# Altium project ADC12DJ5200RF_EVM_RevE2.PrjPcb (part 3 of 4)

## Sheet GPIO2_RevE2.SchDoc: EVM I2C/SPI
size 431 x 279 mm; Date: Not shown in title block; ApprovedBy: Not shown in title block; CheckedBy: Not shown in title block; Author: Not shown in title block; CompanyName: Not shown in title block; DrawnBy: DWG; Engineer: DWG; Organization: Not shown in title block; Address1: Not shown in title block; Address2: Not shown in title block; Address3: Not shown in title block; Address4: Not shown in title block; DocumentNumber: 10; Revision: Use project parameter SCH_Rev; SheetNumber: 10; SheetTotal: 15; PageSetup: Record=PageOptions¦CenterHorizontal=True¦CenterVertical=True¦PrintScale=1.00¦XCorrection=1.00¦YCorrection=1.00¦PrintKind=0¦BorderSize=5000000¦LeftOffset=0¦BottomOffset=0¦Orientation=2¦PaperLength=1000¦PaperWidth=1000¦Scale=100¦PaperSource=15¦PrintQuality=600¦MediaType=1¦DitherType=10¦PaperKind=Letter¦PrintScaleMode=1
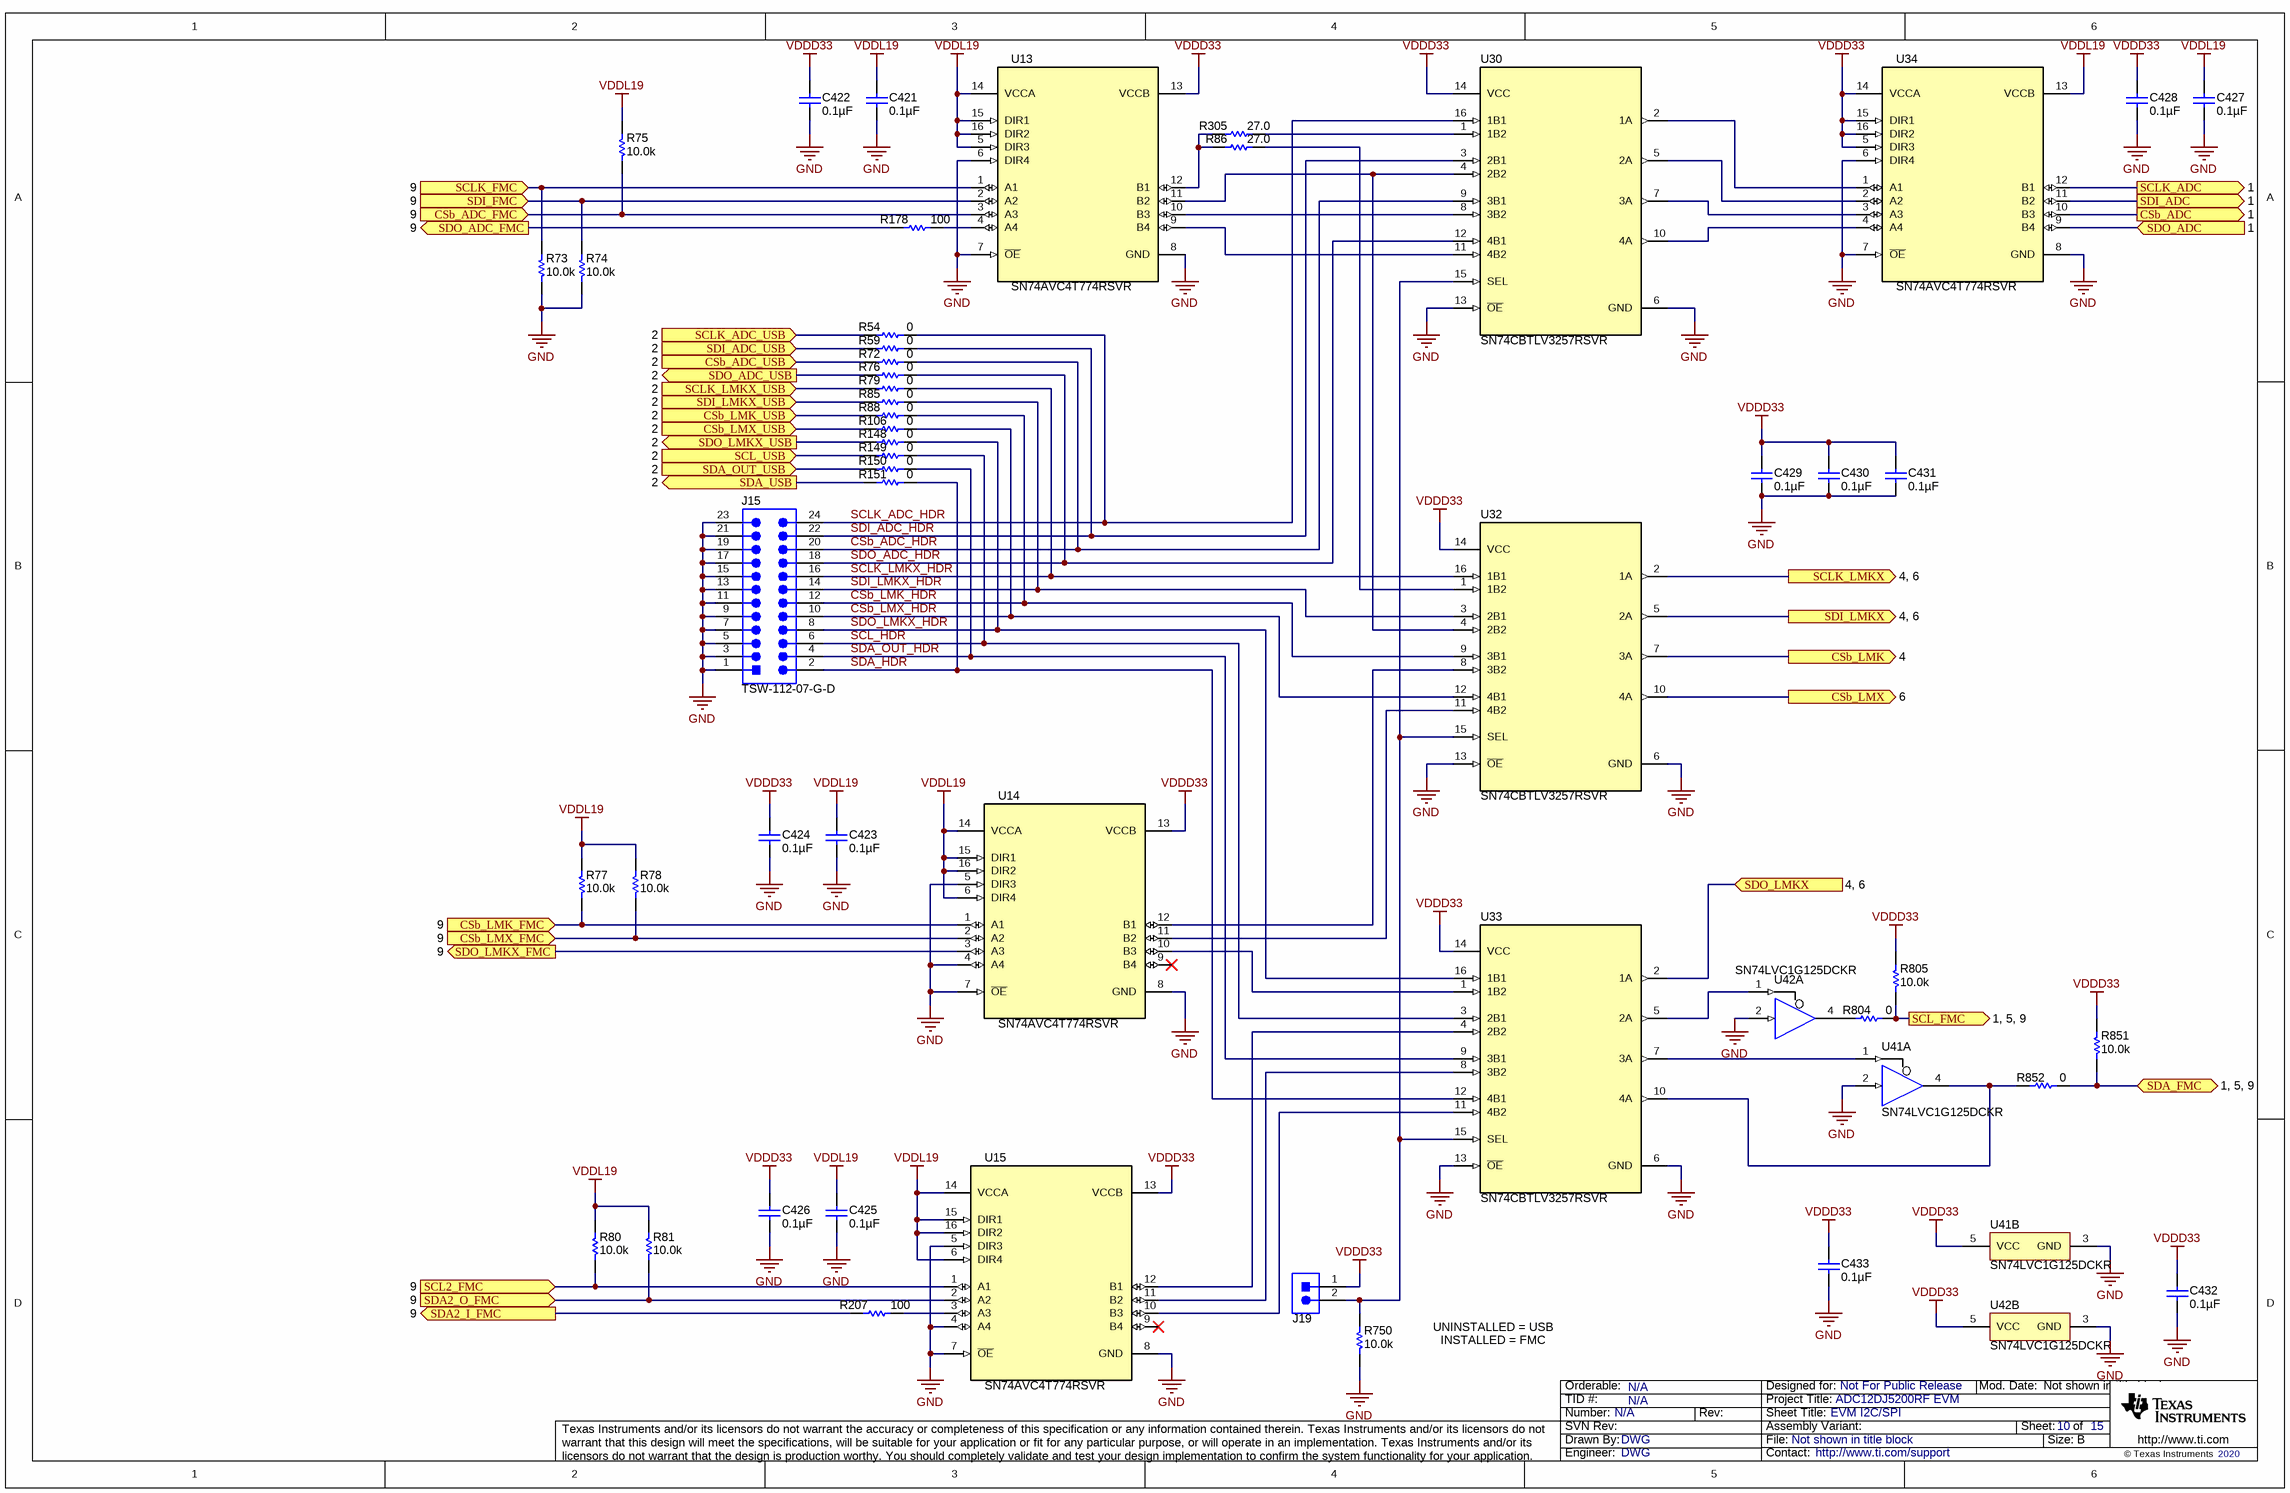
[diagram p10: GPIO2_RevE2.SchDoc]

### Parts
C421  ValueDisplayed: 0.1µF  [0201_033L]  (hidden comment: 0201BB104KW160)
C422  ValueDisplayed: 0.1µF  [0201_033L]  (hidden comment: 0201BB104KW160)
C423  ValueDisplayed: 0.1µF  [0201_033L]  (hidden comment: 0201BB104KW160)
C424  ValueDisplayed: 0.1µF  [0201_033L]  (hidden comment: 0201BB104KW160)
C425  ValueDisplayed: 0.1µF  [0201_033L]  (hidden comment: 0201BB104KW160)
C426  ValueDisplayed: 0.1µF  [0201_033L]  (hidden comment: 0201BB104KW160)
C427  ValueDisplayed: 0.1µF  [0201_033L]  (hidden comment: 0201BB104KW160)
C428  ValueDisplayed: 0.1µF  [0201_033L]  (hidden comment: 0201BB104KW160)
C429  ValueDisplayed: 0.1µF  [0201_033L]  (hidden comment: 0201BB104KW160)
C430  ValueDisplayed: 0.1µF  [0201_033L]  (hidden comment: 0201BB104KW160)
C431  ValueDisplayed: 0.1µF  [0201_033L]  (hidden comment: 0201BB104KW160)
C432  ValueDisplayed: 0.1µF  [0201_033L]  (hidden comment: 0201BB104KW160)
C433  ValueDisplayed: 0.1µF  [0201_033L]  (hidden comment: 0201BB104KW160)
J15  TSW-112-07-G-D  [TSW-112-07-G-D]
J19  5-146261-1  [CONN_5-146261-1]  (value not drawn)
R54  ValueDisplayed: 0  [0201L]  (hidden comment: CRCW02010000Z0ED)
R59  ValueDisplayed: 0  [0201L]  (hidden comment: CRCW02010000Z0ED)
R72  ValueDisplayed: 0  [0201L]  (hidden comment: CRCW02010000Z0ED)
R73  ValueDisplayed: 10.0k  [0201]  (hidden comment: CRCW02010000Z0ED)
R74  ValueDisplayed: 10.0k  [0201]  (hidden comment: CRCW02010000Z0ED)
R75  ValueDisplayed: 10.0k  [0201L]  (hidden comment: RC0201FR-7D10KL)
R76  ValueDisplayed: 0  [0201L]  (hidden comment: CRCW02010000Z0ED)
R77  ValueDisplayed: 10.0k  [0201L]  (hidden comment: RC0201FR-7D10KL)
R78  ValueDisplayed: 10.0k  [0201]  (hidden comment: CRCW02010000Z0ED)
R79  ValueDisplayed: 0  [0201L]  (hidden comment: CRCW02010000Z0ED)
R80  ValueDisplayed: 10.0k  [0201L]  (hidden comment: RC0201FR-7D10KL)
R81  ValueDisplayed: 10.0k  [0201L]  (hidden comment: RC0201FR-7D10KL)
R85  ValueDisplayed: 0  [0201L]  (hidden comment: CRCW02010000Z0ED)
R86  ValueDisplayed: 27.0  [0201L]  (hidden comment: RC0201FR-7D49R9L)
R88  ValueDisplayed: 0  [0201L]  (hidden comment: CRCW02010000Z0ED)
R106  ValueDisplayed: 0  [0201L]  (hidden comment: CRCW02010000Z0ED)
R148  ValueDisplayed: 0  [0201L]  (hidden comment: CRCW02010000Z0ED)
R149  ValueDisplayed: 0  [0201L]  (hidden comment: CRCW02010000Z0ED)
R150  ValueDisplayed: 0  [0201L]  (hidden comment: CRCW02010000Z0ED)
R151  ValueDisplayed: 0  [0201L]  (hidden comment: CRCW02010000Z0ED)
R178  ValueDisplayed: 100  [0201L]  (hidden comment: RC0201FS-7D100RL)
R207  ValueDisplayed: 100  [0201L]  (hidden comment: RC0201FS-7D100RL)
R305  ValueDisplayed: 27.0  [0201L]  (hidden comment: CRCW02010000Z0ED)
R750  ValueDisplayed: 10.0k  [0201L]  (hidden comment: RC0201FR-7D10KL)
R804  ValueDisplayed: 0  [0201L]  (hidden comment: CRCW02010000Z0ED)
R805  ValueDisplayed: 10.0k  [0201]  (hidden comment: RC0201FR-7D10KL)
R851  ValueDisplayed: 10.0k  [0201]  (hidden comment: RC0201FR-7D10KL)
R852  ValueDisplayed: 0  [0201L]  (hidden comment: CRCW02010000Z0ED)
U13  SN74AVC4T774RSVR  [RSV0016A]
U14  SN74AVC4T774RSVR  [RSV0016A]
U15  SN74AVC4T774RSVR  [RSV0016A]
U30  SN74CBTLV3257RSVR  [RSV0016A]
U32  SN74CBTLV3257RSVR  [RSV0016A]
U33  SN74CBTLV3257RSVR  [RSV0016A]
U34  SN74AVC4T774RSVR  [RSV0016A]
U41  SN74LVC1G125DCKR  [DCK0005A_N]  (parts A,B of 2)
U42  SN74LVC1G125DCKR  [DCK0005A_N]  (parts A,B of 2)

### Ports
CSb_ADC (out, see 1), CSb_ADC_FMC (in, see 9), CSb_ADC_USB (in, see 2), CSb_LMK (out, see 4), CSb_LMK_FMC (in, see 9), CSb_LMK_USB (in, see 2), CSb_LMX (out, see 6), CSb_LMX_FMC (in, see 9), CSb_LMX_USB (in, see 2), SCL2_FMC (in, see 9), SCL_FMC (out, see 1, 5, 9), SCL_USB (in, see 2), SCLK_ADC (out, see 1), SCLK_ADC_USB (in, see 2), SCLK_FMC (in, see 9), SCLK_LMKX (out, see 4, 6), SCLK_LMKX_USB (in, see 2), SDA2_I_FMC (out, see 9), SDA2_O_FMC (in, see 9), SDA_FMC (bidir, see 1, 5, 9), SDA_OUT_USB (in, see 2), SDA_USB (out, see 2), SDI_ADC (out, see 1), SDI_ADC_USB (in, see 2), SDI_FMC (in, see 9), SDI_LMKX (out, see 4, 6), SDI_LMKX_USB (in, see 2), SDO_ADC (in, see 1), SDO_ADC_FMC (out, see 9), SDO_ADC_USB (out, see 2), SDO_LMKX (in, see 4, 6), SDO_LMKX_FMC (out, see 9), SDO_LMKX_USB (out, see 2)

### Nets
GND: C421.2 C422.2 C423.2 C424.2 C425.2 C426.2 C427.2 C428.2 C429.2 C430.2 C431.2 C432.2 C433.2 J15.1 J15.3 J15.5 J15.7 J15.9 J15.11 J15.13 J15.15 J15.17 J15.19 J15.21 J15.23 R73.1 R74.1 R750.1 U13.6(DIR4) U13.7(~{OE}) U13.8(GND) U14.4(A4) U14.5(DIR3) U14.7(~{OE}) U14.8(GND) U15.4(A4) U15.5(DIR3) U15.7(~{OE}) U15.8(GND) U30.6(GND) U30.13(~{OE}) U32.6(GND) U32.13(~{OE}) U33.6(GND) U33.13(~{OE}) U34.6(DIR4) U34.7(~{OE}) U34.8(GND) U41.2(A) U41.3(GND) U42.2(A) U42.3(GND)
VDDD33: C422.1 C424.1 C426.1 C428.1 C429.1 C430.1 C431.1 C432.1 C433.1 J19.1 R805.2 R851.2 U13.13(VCCB) U14.13(VCCB) U15.13(VCCB) U30.14(VCC) U32.14(VCC) U33.14(VCC) U34.5(DIR3) U34.14(VCCA) U34.15(DIR1) U34.16(DIR2) U41.5(VCC) U42.5(VCC)
VDDL19: C421.1 C423.1 C425.1 C427.1 R75.1 R77.1 R78.1 R80.1 R81.1 U13.5(DIR3) U13.14(VCCA) U13.15(DIR1) U13.16(DIR2) U14.6(DIR4) U14.14(VCCA) U14.15(DIR1) U14.16(DIR2) U15.6(DIR4) U15.14(VCCA) U15.15(DIR1) U15.16(DIR2) U34.13(VCCB)
CSb_ADC: U34.10(B3) ; port CSb_ADC
CSb_ADC_FMC: R75.2 U13.3(A3) ; port CSb_ADC_FMC
CSb_ADC_HDR: J15.20 R72.2 U30.9(3B1)
CSb_ADC_USB: R72.1 ; port CSb_ADC_USB
CSb_LMK: U32.7(3A) ; port CSb_LMK
CSb_LMK_FMC: R77.2 U14.1(A1) ; port CSb_LMK_FMC
CSb_LMK_HDR: J15.12 R88.2 U32.9(3B1)
CSb_LMK_USB: R88.1 ; port CSb_LMK_USB
CSb_LMX: U32.10(4A) ; port CSb_LMX
CSb_LMX_FMC: R78.2 U14.2(A2) ; port CSb_LMX_FMC
CSb_LMX_HDR: J15.10 R106.2 U32.12(4B1)
CSb_LMX_USB: R106.1 ; port CSb_LMX_USB
SCL2_FMC: R80.2 U15.1(A1) ; port SCL2_FMC
SCL_FMC: R804.2 R805.1 ; port SCL_FMC
SCL_HDR: J15.6 R149.2 U33.3(2B1)
SCL_USB: R149.1 ; port SCL_USB
SCLK_ADC: U34.12(B1) ; port SCLK_ADC
SCLK_ADC_HDR: J15.24 R54.2 U30.16(1B1)
SCLK_ADC_USB: R54.1 ; port SCLK_ADC_USB
SCLK_FMC: R73.2 U13.1(A1) ; port SCLK_FMC
SCLK_LMKX: U32.2(1A) ; port SCLK_LMKX
SCLK_LMKX_HDR: J15.16 R79.2 U32.16(1B1)
SCLK_LMKX_USB: R79.1 ; port SCLK_LMKX_USB
SDA2_I_FMC: R207.2 ; port SDA2_I_FMC
SDA2_O_FMC: R81.2 U15.2(A2) ; port SDA2_O_FMC
SDA_FMC: R851.1 R852.2 ; port SDA_FMC
SDA_HDR: J15.2 R151.2 U33.12(4B1)
SDA_OUT_HDR: J15.4 R150.2 U33.9(3B1)
SDA_OUT_USB: R150.1 ; port SDA_OUT_USB
SDA_USB: R151.1 ; port SDA_USB
SDI_ADC: U34.11(B2) ; port SDI_ADC
SDI_ADC_HDR: J15.22 R59.2 U30.3(2B1)
SDI_ADC_USB: R59.1 ; port SDI_ADC_USB
SDI_FMC: R74.2 U13.2(A2) ; port SDI_FMC
SDI_LMKX: U32.5(2A) ; port SDI_LMKX
SDI_LMKX_HDR: J15.14 R85.2 U32.3(2B1)
SDI_LMKX_USB: R85.1 ; port SDI_LMKX_USB
SDO_ADC: U34.9(B4) ; port SDO_ADC
SDO_ADC_FMC: R178.2 ; port SDO_ADC_FMC
SDO_ADC_HDR: J15.18 R76.2 U30.12(4B1)
SDO_ADC_USB: R76.1 ; port SDO_ADC_USB
SDO_LMKX: U33.2(1A) ; port SDO_LMKX
SDO_LMKX_FMC: U14.3(A3) ; port SDO_LMKX_FMC
SDO_LMKX_HDR: J15.8 R148.2 U33.16(1B1)
SDO_LMKX_USB: R148.1 ; port SDO_LMKX_USB
NetJ19_2: J19.2 R750.2 U30.15(SEL) U32.15(SEL) U33.15(SEL)
NetR86_1: R86.1 U32.1(1B2)
NetR86_2: R86.2 R305.2 U13.12(B1)
NetR178_1: R178.1 U13.4(A4)
NetR207_1: R207.1 U15.3(A3)
NetR305_1: R305.1 U30.1(1B2)
NetR804_1: R804.1 U42.4(Y)
NetR852_1: R852.1 U33.10(4A) U41.4(Y)
NetU13_9: U13.9(B4) U30.11(4B2)
NetU13_10: U13.10(B3) U30.8(3B2)
NetU13_11: U13.11(B2) U30.4(2B2) U32.4(2B2)
NetU14_10: U14.10(B3) U33.1(1B2)
NetU14_11: U14.11(B2) U32.11(4B2)
NetU14_12: U14.12(B1) U32.8(3B2)
NetU15_10: U15.10(B3) U33.11(4B2)
NetU15_11: U15.11(B2) U33.8(3B2)
NetU15_12: U15.12(B1) U33.4(2B2)
NetU30_2: U30.2(1A) U34.1(A1)
NetU30_5: U30.5(2A) U34.2(A2)
NetU30_7: U30.7(3A) U34.3(A3)
NetU30_10: U30.10(4A) U34.4(A4)
NetU33_5: U33.5(2A) U42.1(~{OE})
NetU33_7: U33.7(3A) U41.1(~{OE})

Not connected (* = marked no-connect by the designer): U14 9(B4)*; U15 9(B4)*

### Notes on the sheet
- UNINSTALLED = USB
- INSTALLED = FMC

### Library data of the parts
C421-C433 = CMP-0860981-1: CAP, CERM, 0.1 µF, 16 V,+/- 10%, X7R, 0201; Manufacturer: Passive Plus; Cap_F: 100nF; SizeAreaWB_mm2: 2.08; SizeArea_mm2: 0.18; AEC Qualified: N; AEC Category: Q200; Value: 0.1uF; TaMax_C: 125°C; SizeZ_mm: 0.33; TaMin_C: -55°C; VDC_V: 16V; SizeY_mm: 0.3; U/M: EA; SizeX_mm: 0.6; Cap_Case: 0201
J15 = CMP-0075423-1: Header, 100mil, 12x2, Gold, TH; Manufacturer: Samtec; Pitch_mm: 2.54; Cert_VDE: N; Gender: Male; Cert_CSA: Y; Current_A: 6.3A; Voltage_V: 550V; CT: False; Row_Count: 2; CNHeader: True
J19 = CMP-0054947-1: Header, 100mil, 2x1, Gold, TH; Manufacturer: TE Connectivity; CT: FALSE; Green_REACh: Passed; CNHeader: TRUE; Green_Lifecycle: Active
R54 R59 R72 R76 R79 R85 R88 R106 R148-R151 = CMP-0027008-4: RES, 0, 5%, 0.05 W, 0201; Manufacturer: Vishay-Dale; Power_W: 50mW; TempCo: ppm/C; Value_Code: 0000; Value: 0; EIA_Code: E24; SizeX_mm: 0.6; SizeY_mm: 0.3; SizeZ_mm: 0.26; Value2: 0.05W; SizeArea_mm2: 0.18; AEC Qualified: N; AEC Category: Q200
R73 R78 = CMP-0027945-1: RES, 10.0 k, 1%, 0.05 W, 0201; Manufacturer: Yageo America; PartNumber: RC0201FR-7D10KL; Power_W: 50mW; TempCo: 200 ppm/C; Value_Code: 10k0; U/M: EA; Value: 10.0k; EIA_Code: E96; Res_ohm: 10k; SizeX_mm: 0.6; SizeY_mm: 0.3; SizeZ_mm: 0.26; Value2: 0.05W; SizeArea_mm2: 0.18; CompType: Resistor; AEC Qualified: N; VDC_V: 25V; AEC Category: Q200
R74 = CMP-0027945-1: RES, 10.0 k, 1%, 0.05 W, 0201; Manufacturer: Yageo America; PartNumber: RC0201FR-7D10KL; Power_W: 50mW; TempCo: 200 ppm/C; Value_Code: 10k0; U/M: EA; Value: 10.0k; EIA_Code: E96; Res_ohm: 10k; SizeX_mm: 0.6; SizeY_mm: 0.3; SizeZ_mm: 0.26; Value2: 0.05W; SizeArea_mm2: 0.18; AEC Qualified: N; VDC_V: 25V; AEC Category: Q200
R75 R77 R81 R750 R805 R851 = CMP-0027945-1: RES, 10.0 k, 1%, 0.05 W, 0201; Manufacturer: Yageo America; Power_W: 50mW; TempCo: 200 ppm/C; Value_Code: 10k0; U/M: EA; Value: 10.0k; EIA_Code: E96; Res_ohm: 10k; SizeX_mm: 0.6; SizeY_mm: 0.3; SizeZ_mm: 0.26; Value2: 0.05W; SizeArea_mm2: 0.18; CompType: Resistor; AEC Qualified: N; VDC_V: 25V; AEC Category: Q200
R80 = CMP-0027945-1: RES, 10.0 k, 1%, 0.05 W, 0201; Manufacturer: Yageo America; Power_W: 50mW; TempCo: 200 ppm/C; Value_Code: 10k0; U/M: EA; Value: 10.0k; EIA_Code: E96; Res_ohm: 10k; SizeX_mm: 0.6; SizeY_mm: 0.3; SizeZ_mm: 0.26; Value2: 0.05W; SizeArea_mm2: 0.18; AEC Qualified: N; VDC_V: 25V; AEC Category: Q200
R86 R305 = CMP-0027540-1: RES, 27.0, 1%, 0.05 W, 0201; Manufacturer: Yageo America; PartNumber: RC0201FR-0727RL; Power_W: 50mW; TempCo: 200 ppm/C; Value_Code: 27R0; U/M: EA; Value: 27.0; Res_ohm: 27; SizeX_mm: 0.6; SizeY_mm: 0.3; SizeZ_mm: 0.26; Value2: 0.05W; SizeArea_mm2: 0.18; CompType: Resistor; AEC Qualified: N; VDC_V: 25V; AEC Category: Q200
R178 R207 = CMP-0028070-1: RES, 100, 1%, 0.05 W, 0201; Manufacturer: Yageo America; Power_W: 50mW; TempCo: 200 ppm/C; Value_Code: 100R; U/M: EA; Value: 100; EIA_Code: E96; SizeX_mm: 0.6; SizeY_mm: 0.3; SizeZ_mm: 0.26; Value2: 0.05W; SizeArea_mm2: 0.18; AEC Qualified: N; VDC_V: 25V; AEC Category: Q200
R804 R852 = CMP-0027008-4: RES, 0, 5%, 0.05 W, 0201; Manufacturer: Vishay-Dale; Power_W: 50mW; TempCo: ppm/C; Value_Code: 0000; Value: 0; EIA_Code: E24; SizeX_mm: 0.6; SizeY_mm: 0.3; SizeZ_mm: 0.26; Value2: 0.05W; SizeArea_mm2: 0.18; CompType: Resistor; AEC Qualified: N; AEC Category: Q200
U13-U15 U34 = CMP-0066452-2: 4-Bit Dual-Supply Bus Transceiver With Configurable Voltage-Level Shifting and 3-State Outputs, RSV0016A (UQFN-16); Alternate Manufacturer: Texas Instruments; Green_Lifecycle: Active; SizeAreaWB_mm2: 10.08; Green_REACh: Passed; SizeZ_mm: 0.55; SizeX_mm: 1.8; SizeY_mm: 2.6; SizeArea_mm2: 4.68; CompType: IC; AEC Category: Q200; AEC Qualified: N; Rating: Catalog
U30 U32 U33 = CMP-0066255-1: Low-Voltage 4-Bit 1-of-2 FET Multiplexer/Demultiplexer, RSV0016A (UQFN-16); Alternate Manufacturer: Texas Instruments; SizeAreaWB_mm2: 10.08; U/M: EA; SizeZ_mm: 0.55; SizeX_mm: 1.8; SizeY_mm: 2.6; SizeArea_mm2: 4.68; CompType: IC
U41 U42 = CMP-0051326-3: Single Bus Buffer Gate With 3-State Outputs, DCK0005A, LARGE T&R; Manufacturer: Texas Instruments; Bits(#): 1; tpd @ Nom Voltage(Max)(ns): 9,5.5,4.5,4; 3-State Output: Yes; Output Type: CMOS; Sub-Family: Non-Inverting Buffer/Driver; Logic: True; Output Drive (IOL/IOH)(Max)(mA): 32/-32; Voltage(Nom)(V): 1.8,2.5,3.3,5; ICC @ Nom Voltage(Max)(mA): 0.01; Technology Family: LVC; VCC(Min)(V): 1.65; VCC(Max)(V): 5.5; F @ Nom Voltage(Max)(Mhz): 150; Rating: Catalog; Input Type: CMOS/TTL; Schmitt Trigger: No; AEC Category: Q200; AEC Qualified: N; CompType: IC; SizeAreaWB_mm2: 9.3; SizeArea_mm2: 4.2; SizeX_mm: 2.1; SizeY_mm: 2.0; SizeZ_mm: 1.1

## Sheet Misc_RevE2.SchDoc: EVM Misc
size 431 x 279 mm; Date: Not shown in title block; ApprovedBy: Not shown in title block; CheckedBy: Not shown in title block; Author: Not shown in title block; CompanyName: Not shown in title block; DrawnBy: DWG; Engineer: DWG; Organization: Not shown in title block; Address1: Not shown in title block; Address2: Not shown in title block; Address3: Not shown in title block; Address4: Not shown in title block; DocumentNumber: 11; Revision: Use project parameter SCH_Rev; SheetNumber: 11; SheetTotal: 15; PageSetup: Record=PageOptions¦CenterHorizontal=True¦CenterVertical=True¦PrintScale=1.00¦XCorrection=1.00¦YCorrection=1.00¦PrintKind=0¦BorderSize=5000000¦LeftOffset=0¦BottomOffset=0¦Orientation=2¦PaperLength=1000¦PaperWidth=1000¦Scale=100¦PaperSource=15¦PrintQuality=600¦MediaType=1¦DitherType=10¦PaperKind=Letter¦PrintScaleMode=1
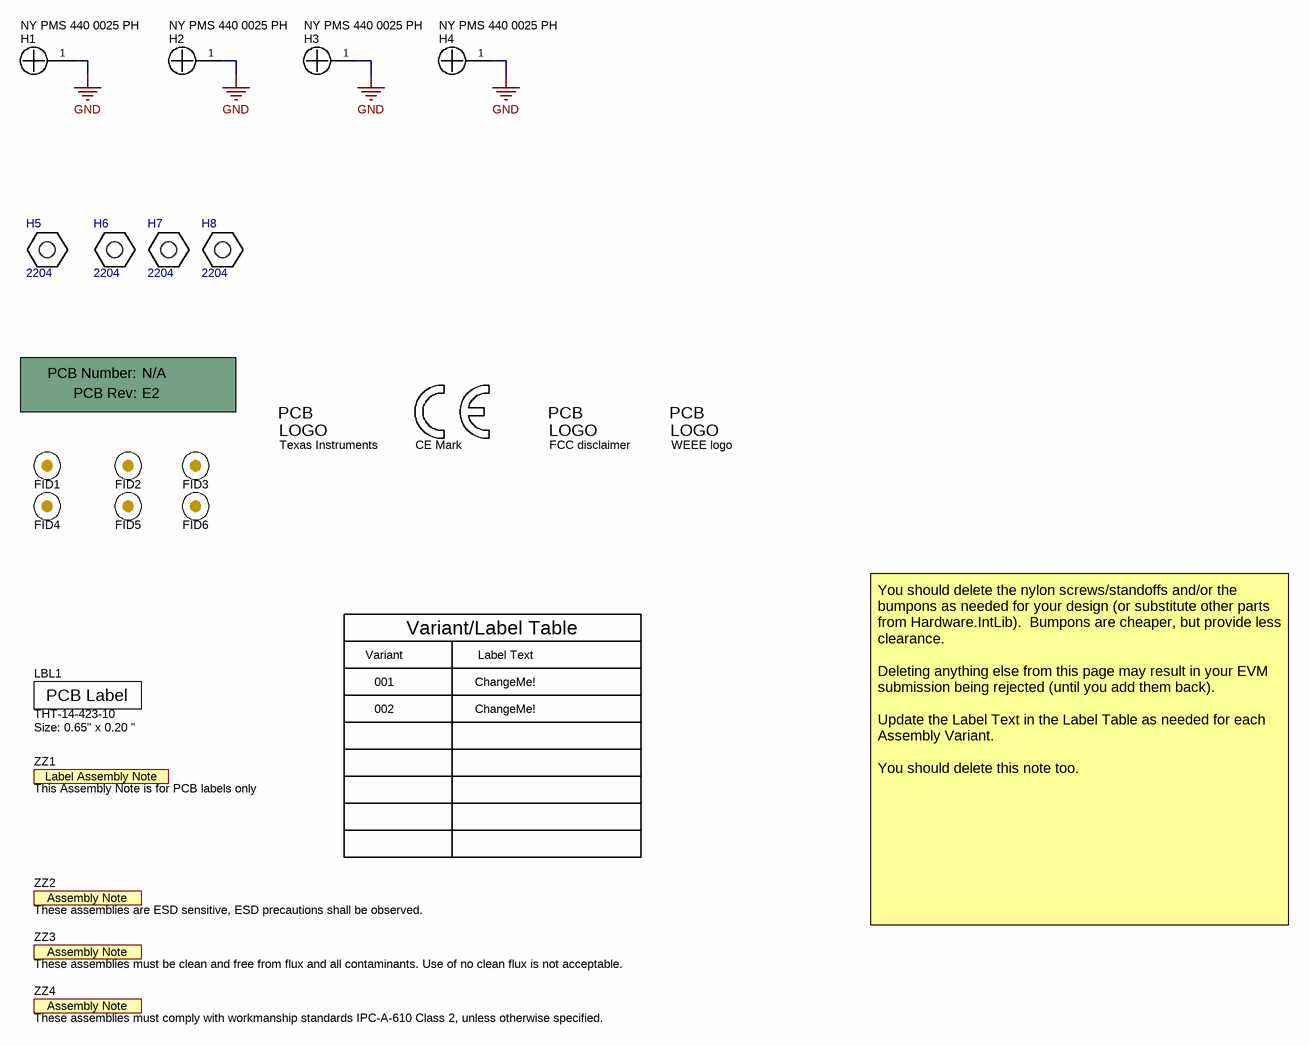
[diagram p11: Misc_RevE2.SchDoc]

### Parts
!PCB  Printed Circuit Board  (value not drawn)  (mechanical)
FID1  Fiducial  [Fiducial10-20]  (value not drawn)
FID2  Fiducial  [Fiducial10-20]  (value not drawn)
FID3  Fiducial  [Fiducial10-20]  (value not drawn)
FID4  Fiducial  [Fiducial10-20]  (value not drawn)
FID5  Fiducial  [Fiducial10-20]  (value not drawn)
FID6  Fiducial  [Fiducial10-20]  (value not drawn)
H1  NY PMS 440 0025 PH  [NY PMS 440 0025 PH]
H2  NY PMS 440 0025 PH  [NY PMS 440 0025 PH]
H3  NY PMS 440 0025 PH  [NY PMS 440 0025 PH]
H4  NY PMS 440 0025 PH  [NY PMS 440 0025 PH]
H5  2204  [Keystone_2204]
H6  2204  [Keystone_2204]
H7  2204  [Keystone_2204]
H8  2204  [Keystone_2204]
LBL1  THT-14-423-10  Note: Size: 0.65" x 0.20 "  [Label_650x200]
Logo1  Texas Instruments  [TI_Stacked_Overlay_Small]  (no BOM)
Logo2  CE Mark  [CE_Mark_5mm]  (no BOM)
Logo3  FCC disclaimer  [FCC_disclaimer]  (no BOM)
Logo4  WEEE logo  [WEEE_Minimum]  (no BOM)
ZZ1  This Assembly Note is for PCB labels only  [AssemblyNoteLabel]  (no BOM)
ZZ2  These assemblies are ESD sensitive, ESD precautions shall be observed.  [AssemblyNote]  (no BOM)
ZZ3  These assemblies must be clean and free from flux and all contaminants. Use of no clean flux is not acceptable.  [AssemblyNote]  (no BOM)
ZZ4  These assemblies must comply with workmanship standards IPC-A-610 Class 2, unless otherwise specified.  [AssemblyNote]  (no BOM)

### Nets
GND: H1.1 H2.1 H3.1 H4.1

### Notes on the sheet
- Variant/Label Table
- Variant
- 001
- Label Text
- ChangeMe!
- 002
- You should delete the nylon screws/standoffs and/or the bumpons as needed for your design (or substitute other parts from Hardware.IntLib).  Bumpons are cheaper, but provide less clearance.
  Deleting anything else from this page may result in your EVM submission being rejected (until you add them back).
  Update the Label Text in the Label Table as needed for each Assembly Variant.
  You should delete this note too.

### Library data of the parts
!PCB = CMP-0003618-2: Manufacturer: Any
FID1-FID6 = CMP-0077181-1: Fiducial mark.  There is nothing to buy or mount.
H1-H4 = CMP-0003617-1: Machine Screw, Round, #4-40 x 1/4, Nylon, Philips panhead; Manufacturer: B&F Fastener Supply; CompType: Hardware
H5-H8 = CMP-0003917-1: Manufacturer: Keystone; CompType: Standoff
LBL1 = CMP-0003625-1: Thermal Transfer Printable Labels, 0.650" W x 0.200" H - 10,000 per roll; Manufacturer: Brady; CompType: Label
Logo1 = CMP-0074838-1: Texas Instrument Corporate Signature; SymbolCreator: a0412235; Lib Reference: TI_Logo; Library Reference: Logo
Logo2 = CMP-0074844-1: SymbolCreator: a0412235
Logo3 = CMP-0074847-1: FCC_disclaimer; Library Reference: Logo
Logo4 = CMP-0074769-1
ZZ1 = CMP-0003616-3
ZZ2 = CMP-0077236-1
ZZ3 = CMP-0077237-1
ZZ4 = CMP-0077238-1

## Sheet Power1_RevE2.SchDoc: EVM Power
size 431 x 279 mm; Date: Not shown in title block; ApprovedBy: Not shown in title block; CheckedBy: Not shown in title block; Author: Not shown in title block; CompanyName: Not shown in title block; DrawnBy: DWG; Engineer: DWG; Organization: Not shown in title block; Address1: Not shown in title block; Address2: Not shown in title block; Address3: Not shown in title block; Address4: Not shown in title block; DocumentNumber: 12; Revision: Use project parameter SCH_Rev; SheetNumber: 12; SheetTotal: 15; PageSetup: Record=PageOptions¦CenterHorizontal=True¦CenterVertical=True¦PrintScale=1.00¦XCorrection=1.00¦YCorrection=1.00¦PrintKind=0¦BorderSize=5000000¦LeftOffset=0¦BottomOffset=0¦Orientation=2¦PaperLength=1000¦PaperWidth=1000¦Scale=100¦PaperSource=15¦PrintQuality=600¦MediaType=1¦DitherType=10¦PaperKind=Letter¦PrintScaleMode=1
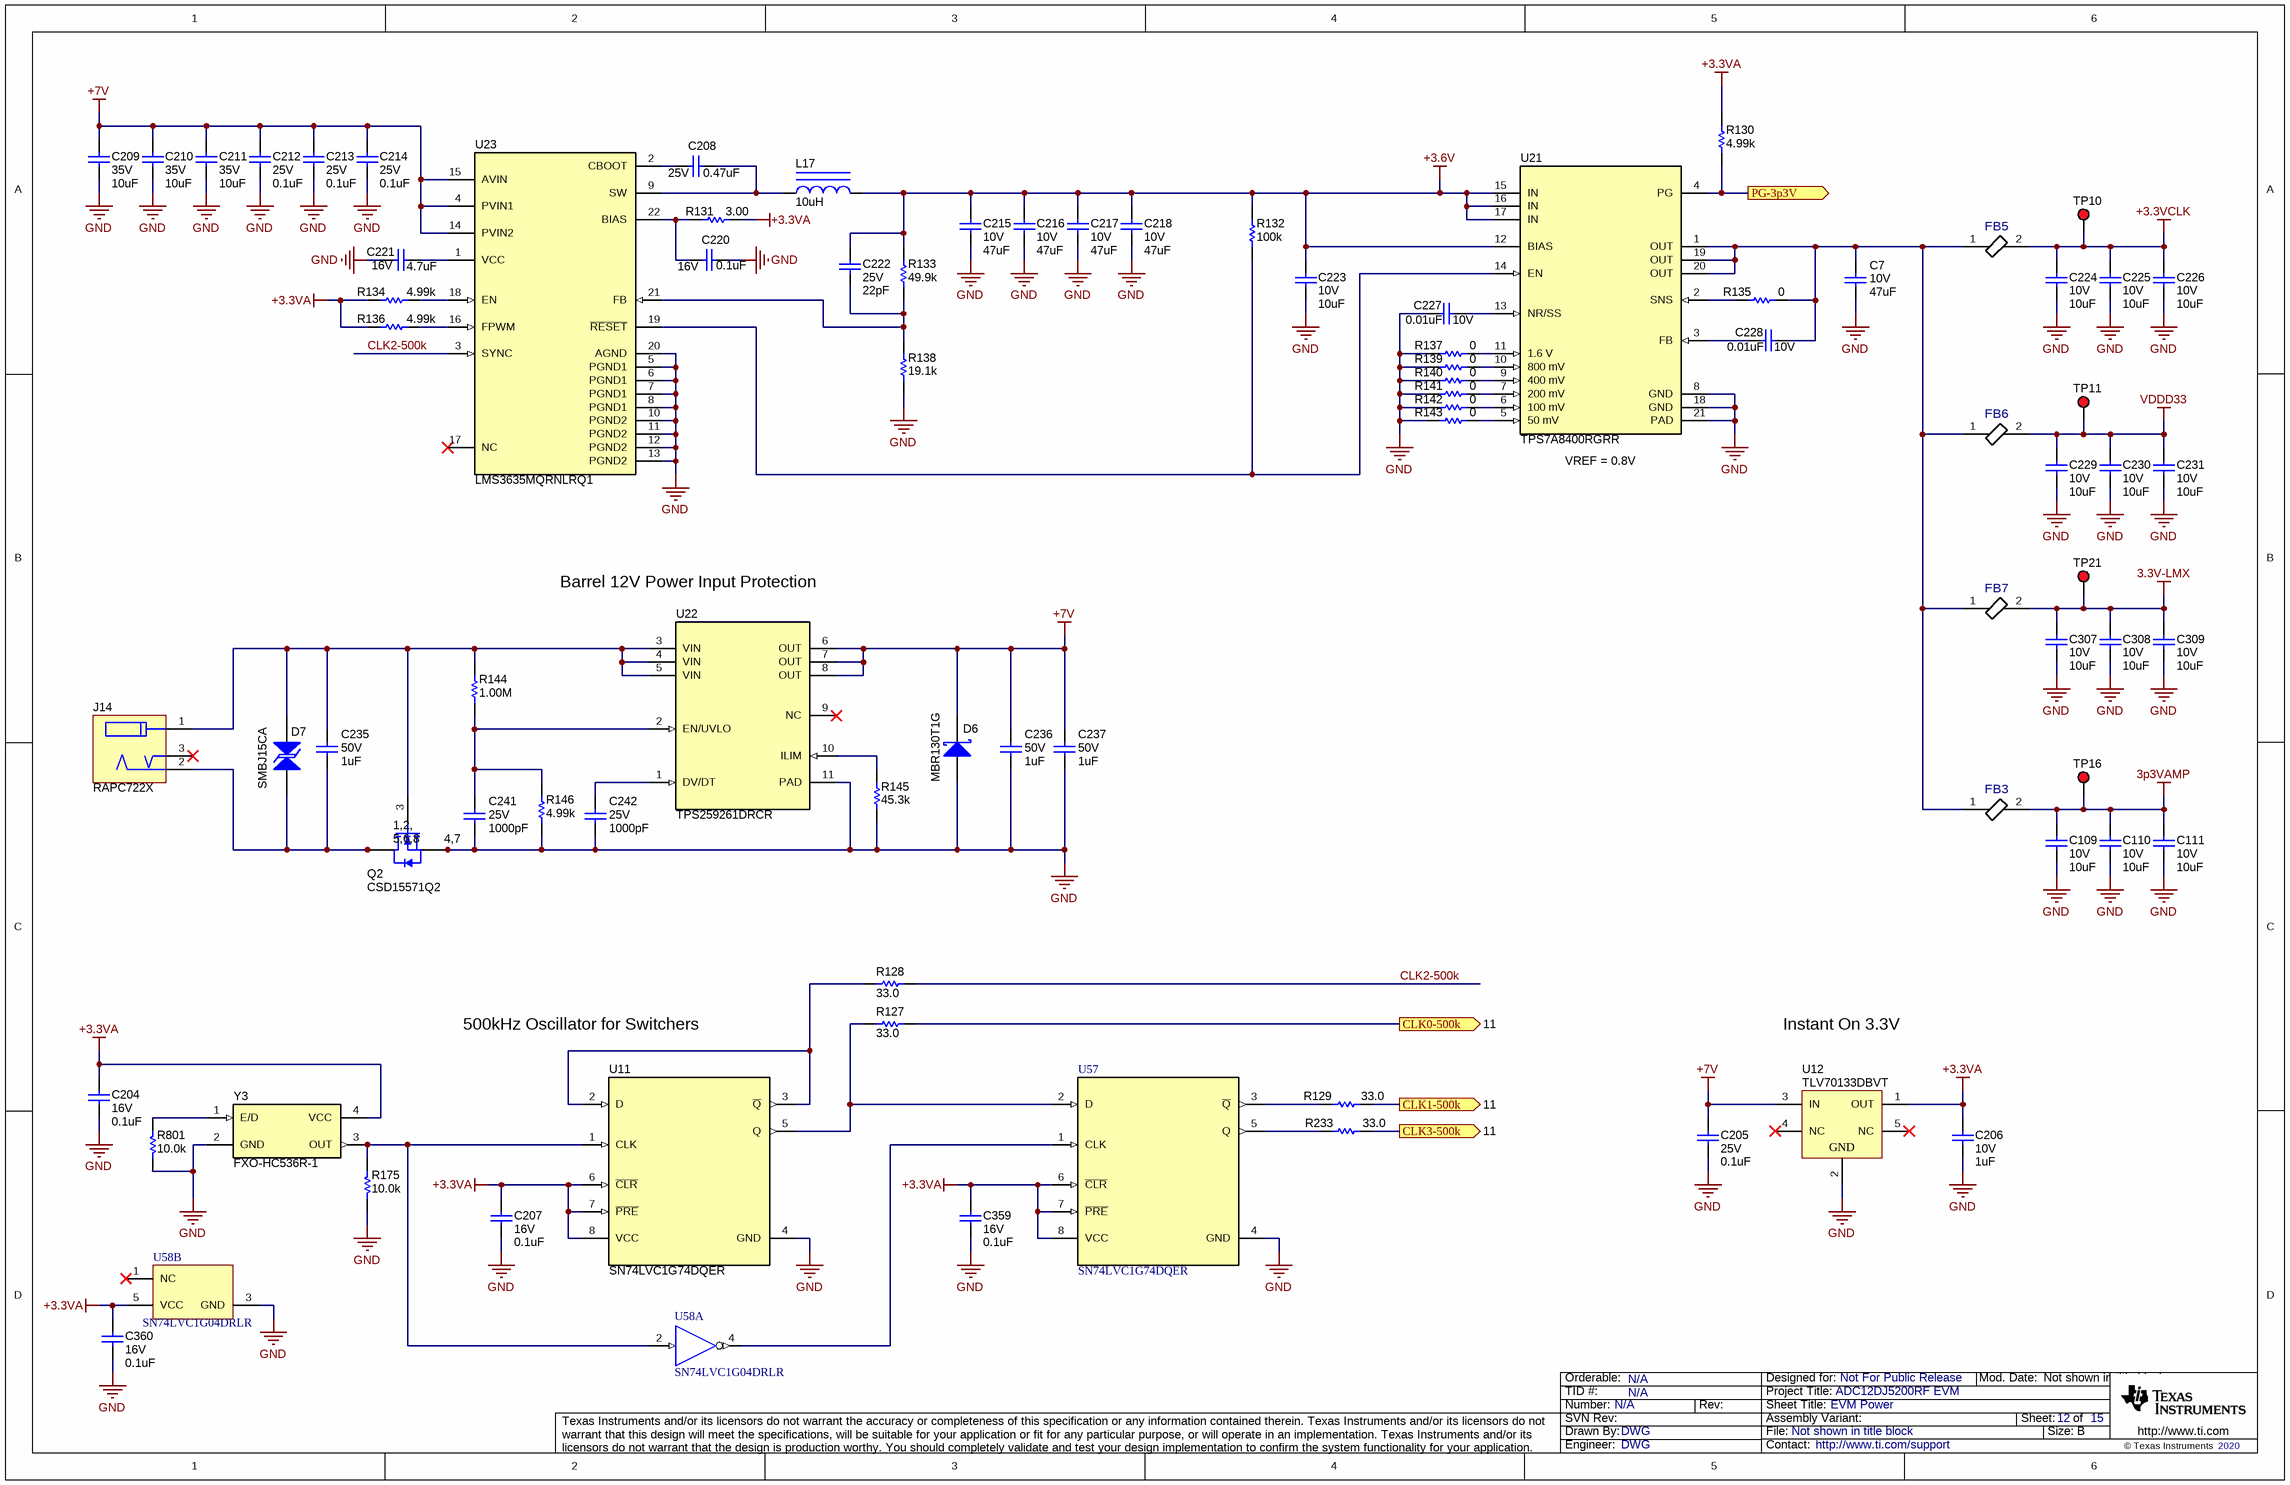
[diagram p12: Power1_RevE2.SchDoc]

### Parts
C7  VDC_V: 10V  ValueDisplayed: 47uF  [1210_270]  (hidden comment: GRM32ER71A476KE15L)
C109  VDC_V: 10V  ValueDisplayed: 10uF  [0603]  (hidden comment: GRM188Z71A106MA73D)
C110  VDC_V: 10V  ValueDisplayed: 10uF  [0603]  (hidden comment: GRM188Z71A106MA73D)
C111  VDC_V: 10V  ValueDisplayed: 10uF  [0603]  (hidden comment: GRM188Z71A106MA73D)
C204  VDC_V: 16V  ValueDisplayed: 0.1uF  [0201]  (hidden comment: GRM033Z71C104KE14D)
C205  VDC_V: 25V  ValueDisplayed: 0.1uF  [0603]  (hidden comment: C1608X7R1E104K080AA)
C206  VDC_V: 10V  ValueDisplayed: 1uF  [0603]  (hidden comment: GRM188R71A105KA61D)
C207  VDC_V: 16V  ValueDisplayed: 0.1uF  [0201]  (hidden comment: GRM033Z71C104KE14D)
C208  VDC_V: 25V  ValueDisplayed: 0.47uF  [0603]  (hidden comment: GRM188R71E474KA12D)
C209  VDC_V: 35V  ValueDisplayed: 10uF  [1206_180]  (hidden comment: C3216X7R1V106K160AC)
C210  VDC_V: 35V  ValueDisplayed: 10uF  [1206_180]  (hidden comment: C3216X7R1V106K160AC)
C211  VDC_V: 35V  ValueDisplayed: 10uF  [1206_180]  (hidden comment: C3216X7R1V106K160AC)
C212  VDC_V: 25V  ValueDisplayed: 0.1uF  [0603]  (hidden comment: C1608X7R1E104K080AA)
C213  VDC_V: 25V  ValueDisplayed: 0.1uF  [0603]  (hidden comment: C1608X7R1E104K080AA)
C214  VDC_V: 25V  ValueDisplayed: 0.1uF  [0603]  (hidden comment: C1608X7R1E104K080AA)
C215  VDC_V: 10V  ValueDisplayed: 47uF  [1210_270]  (hidden comment: GRM32ER71A476KE15L)
C216  VDC_V: 10V  ValueDisplayed: 47uF  [1210_270]  (hidden comment: GRM32ER71A476KE15L)
C217  VDC_V: 10V  ValueDisplayed: 47uF  [1210_270]  (hidden comment: GRM32ER71A476KE15L)
C218  VDC_V: 10V  ValueDisplayed: 47uF  [1210_270]  (hidden comment: GRM32ER71A476KE15L)
C220  VDC_V: 16V  ValueDisplayed: 0.1uF  [0201]  (hidden comment: GRM033Z71C104KE14D)
C221  VDC_V: 16V  ValueDisplayed: 4.7uF  [0603]  (hidden comment: GRM188Z71C475KE21D)
C222  VDC_V: 25V  ValueDisplayed: 22pF  [0201_033]  (hidden comment: GCM0335C1E220JD03D)
C223  VDC_V: 10V  ValueDisplayed: 10uF  [0603]  (hidden comment: GRM188Z71A106MA73D)
C224  VDC_V: 10V  ValueDisplayed: 10uF  [0603]  (hidden comment: GRM188Z71A106MA73D)
C225  VDC_V: 10V  ValueDisplayed: 10uF  [0603]  (hidden comment: GRM188Z71A106MA73D)
C226  VDC_V: 10V  ValueDisplayed: 10uF  [0603]  (hidden comment: GRM188Z71A106MA73D)
C227  VDC_V: 10V  ValueDisplayed: 0.01uF  [0201]  (hidden comment: GRM033R71A103KA01D)
C228  VDC_V: 10V  ValueDisplayed: 0.01uF  [0201]  (hidden comment: GRM033R71A103KA01D)
C229  VDC_V: 10V  ValueDisplayed: 10uF  [0603]  (hidden comment: GRM188Z71A106MA73D)
C230  VDC_V: 10V  ValueDisplayed: 10uF  [0603]  (hidden comment: GRM188Z71A106MA73D)
C231  VDC_V: 10V  ValueDisplayed: 10uF  [0603]  (hidden comment: GRM188Z71A106MA73D)
C235  VDC_V: 50V  ValueDisplayed: 1uF  [0805_HV]  (hidden comment: C0805C105K5RACTU)
C236  VDC_V: 50V  ValueDisplayed: 1uF  [0805_HV]  (hidden comment: C0805C105K5RACTU)
C237  VDC_V: 50V  ValueDisplayed: 1uF  [0805_HV]  (hidden comment: C0805C105K5RACTU)
C241  VDC_V: 25V  ValueDisplayed: 1000pF  [0201_033]  (hidden comment: GRM033R71E102KA01D)
C242  VDC_V: 25V  ValueDisplayed: 1000pF  [0201_033]  (hidden comment: GRM033R71E102KA01D)
C307  VDC_V: 10V  ValueDisplayed: 10uF  [0603]  (hidden comment: GRM188Z71A106MA73D)
C308  VDC_V: 10V  ValueDisplayed: 10uF  [0603]  (hidden comment: GRM188Z71A106MA73D)
C309  VDC_V: 10V  ValueDisplayed: 10uF  [0603]  (hidden comment: GRM188Z71A106MA73D)
C359  VDC_V: 16V  ValueDisplayed: 0.1uF  [0201]  (hidden comment: GRM033Z71C104KE14D)
C360  VDC_V: 16V  ValueDisplayed: 0.1uF  [0201]  (hidden comment: GRM033Z71C104KE14D)
D6  MBR130T1G  [SOD-123]
D7  SMBJ15CA  [SMB-Bi]
FB3  BLM21SN300SN1D  [FP-BLM21SN300SN1D_0805-MFG]  (value not drawn)
FB5  BLM21SN300SN1D  [FP-BLM21SN300SN1D_0805-MFG]  (value not drawn)
FB6  BLM21SN300SN1D  [FP-BLM21SN300SN1D_0805-MFG]  (value not drawn)
FB7  BLM21SN300SN1D  [FP-BLM21SN300SN1D_0805-MFG]  (value not drawn)
J14  RAPC722X  [CONN_RAPC722X]
L17  ValueDisplayed: 10uH  [XAL8080]  (hidden comment: XAL8080-103MEB)
Q2  CSD15571Q2  [DQK0006C]
R127  ValueDisplayed: 33.0  [0201]  (hidden comment: RC0201FR-0733RL)
R128  ValueDisplayed: 33.0  [0201]  (hidden comment: RC0201FR-0733RL)
R129  ValueDisplayed: 33.0  [0201]  (hidden comment: RC0201FR-0733RL)
R130  ValueDisplayed: 4.99k  [0201]  (hidden comment: RC0201FS-7D4K99L)
R131  ValueDisplayed: 3.00  [0201]  (hidden comment: RC0201FR-073RL)
R132  ValueDisplayed: 100k  [0201]  (hidden comment: RC0201FS-7D4K99L)
R133  ValueDisplayed: 49.9k  [0201]  (hidden comment: RC0201FR-7D49K9L)
R134  ValueDisplayed: 4.99k  [0201]  (hidden comment: RC0201FS-7D4K99L)
R135  ValueDisplayed: 0  [0201]  (hidden comment: CRCW02010000Z0ED)
R136  ValueDisplayed: 4.99k  [0201]  (hidden comment: RC0201FS-7D4K99L)
R137  ValueDisplayed: 0  [0201]  (hidden comment: CRCW02010000Z0ED)
R138  ValueDisplayed: 19.1k  [0201]  (hidden comment: RC0201FR-0719K1L)
R139  ValueDisplayed: 0  [0201]  (hidden comment: CRCW02010000Z0ED)
R140  ValueDisplayed: 0  [0201]  (hidden comment: CRCW02010000Z0ED)
R141  ValueDisplayed: 0  [0201]  (hidden comment: CRCW02010000Z0ED)
R142  ValueDisplayed: 0  [0201]  (hidden comment: CRCW02010000Z0ED)
R143  ValueDisplayed: 0  [0201]  (hidden comment: CRCW02010000Z0ED)
R144  ValueDisplayed: 1.00M  [0201]  (hidden comment: RC0201FR-7D1ML)
R145  ValueDisplayed: 45.3k  [0201]  (hidden comment: RC0201FR-7D45K3L)
R146  ValueDisplayed: 4.99k  [0201]  (hidden comment: RC0201FS-7D4K99L)
R175  ValueDisplayed: 10.0k  [0201L]  (hidden comment: RC0201FR-7D10KL)
R233  ValueDisplayed: 33.0  [0201]  (hidden comment: RC0201FR-0733RL)
R801  ValueDisplayed: 10.0k  [0201L]  (hidden comment: RC0201FR-7D10KL)
TP10  5000  [Keystone5000]  (value not drawn)
TP11  5000  [Keystone5000]  (value not drawn)
TP16  5000  [Keystone5000]  (value not drawn)
TP21  5000  [Keystone5000]  (value not drawn)
U11  SN74LVC1G74DQER  [DQE0008A]
U12  TLV70133DBVT  [DBV0005A_N]
U21  TPS7A8400RGRR  [RGR0020A]
U22  TPS259261DRCR  [DRC0010J]
U23  LMS3635MQRNLRQ1  [RNL0022A]
U57  SN74LVC1G74DQER  [DQE0008A]
U58  SN74LVC1G04DRLR  [DRL0005A]  (parts A,B of 2)
Y3  FXO-HC536R-1  [FOX_FXO-HC5]

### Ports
CLK0-500k (out, see 11), CLK1-500k (out, see 11), CLK3-500k (out, see 11), PG-3p3V (out)

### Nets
3.3V-LMX: C307.1 C308.1 C309.1 FB7.2 TP21.1
3p3VAMP: C109.1 C110.1 C111.1 FB3.2 TP16.1
+3.3VA: C204.2 C206.1 C207.2 C359.2 C360.2 R130.1 R131.2 R134.2 R136.2 U11.6(~{CLR}) U11.7(~{PRE}) U11.8(VCC) U12.1(OUT) U57.6(~{CLR}) U57.7(~{PRE}) U57.8(VCC) U58.5(VCC) Y3.4(VCC)
+3.3VCLK: C224.1 C225.1 C226.1 FB5.2 TP10.1
+3.6V: C215.1 C216.1 C217.1 C218.1 C222.1 C223.1 L17.2 R132.2 R133.2 U21.12(BIAS) U21.15(IN) U21.16(IN) U21.17(IN)
+7V: C205.1 C209.1 C210.1 C211.1 C212.1 C213.1 C214.1 C236.1 C237.1 D6.1(K) U12.3(IN) U22.6(OUT) U22.7(OUT) U22.8(OUT) U23.4(PVIN1) U23.14(PVIN2) U23.15(AVIN)
GND: C7.2 C109.2 C110.2 C111.2 C204.1 C205.2 C206.2 C207.1 C209.2 C210.2 C211.2 C212.2 C213.2 C214.2 C215.2 C216.2 C217.2 C218.2 C220.1 C221.1 C223.2 C224.2 C225.2 C226.2 C227.2 C229.2 C230.2 C231.2 C236.2 C237.2 C241.2 C242.2 C307.2 C308.2 C309.2 C359.1 C360.1 D6.2(A) Q2.4(S) Q2.7(S) R137.1 R138.1 R139.1 R140.1 R141.1 R142.1 R143.1 R145.1 R146.2 R175.1 R801.1 U11.4(GND) U12.2(GND) U21.8(GND) U21.18(GND) U21.21(PAD) U22.11(PAD) U23.5(PGND1) U23.6(PGND1) U23.7(PGND1) U23.8(PGND1) U23.10(PGND2) U23.11(PGND2) U23.12(PGND2) U23.13(PGND2) U23.20(AGND) U57.4(GND) U58.3(GND) Y3.2(GND)
VDDD33: C229.1 C230.1 C231.1 FB6.2 TP11.1
CLK0-500k: R127.2 ; port CLK0-500k
CLK1-500k: R129.2 ; port CLK1-500k
CLK2-500k: R128.2 U23.3(SYNC)
CLK3-500k: R233.2 ; port CLK3-500k
PG-3p3V: R130.2 U21.4(PG) ; port PG-3p3V
NetC7_1: C7.1 C228.1 FB3.1 FB5.1 FB6.1 FB7.1 R135.2 U21.1(OUT) U21.19(OUT) U21.20(OUT)
NetC208_1: C208.1 U23.2(CBOOT)
NetC208_2: C208.2 L17.1 U23.9(SW)
NetC220_2: C220.2 R131.1 U23.22(BIAS)
NetC221_2: C221.2 U23.1(VCC)
NetC222_2: C222.2 R133.1 R138.2 U23.21(FB)
NetC227_1: C227.1 U21.13(NR/SS)
NetC228_2: C228.2 U21.3(FB)
NetC235_1: C235.1 D7.2 J14.1 Q2.3(G) R144.2 U22.3(VIN) U22.4(VIN) U22.5(VIN)
NetC235_2: C235.2 D7.1 J14.2 Q2.1(D) Q2.2(D) Q2.5(D) Q2.6(D) Q2.8(D)
NetC241_1: C241.1 R144.1 R146.1 U22.2(EN/UVLO)
NetC242_1: C242.1 U22.1(DV/DT)
NetR127_1: R127.1 U11.5(Q) U57.2(D)
NetR128_1: R128.1 U11.2(D) U11.3(~{Q})
NetR129_1: R129.1 U57.3(~{Q})
NetR132_1: R132.1 U21.14(EN) U23.19(~{RESET})
NetR134_1: R134.1 U23.18(EN)
NetR135_1: R135.1 U21.2(SNS)
NetR136_1: R136.1 U23.16(FPWM)
NetR137_2: R137.2 U21.11(1.6_V)
NetR139_2: R139.2 U21.10(800_mV)
NetR140_2: R140.2 U21.9(400_mV)
NetR141_2: R141.2 U21.7(200_mV)
NetR142_2: R142.2 U21.6(100_mV)
NetR143_2: R143.2 U21.5(50_mV)
NetR145_2: R145.2 U22.10(ILIM)
NetR175_2: R175.2 U11.1(CLK) U58.2(A) Y3.3(OUT)
NetR233_1: R233.1 U57.5(Q)
NetR801_2: R801.2 Y3.1(E/D)
NetU57_1: U57.1(CLK) U58.4(Y)

Not connected (* = marked no-connect by the designer): J14 3*; U12 4(NC)* 5(NC)*; U22 9(NC)*; U23 17(NC)*; U58 1(NC)*

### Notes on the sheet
- (near U21) VREF = 0.8V
- Barrel 12V Power Input Protection
- 500kHz Oscillator for Switchers
- Instant On 3.3V

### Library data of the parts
C7 C215-C218 = CMP-0009220-2: CAP, CERM, 47 uF, 10 V, +/- 10%, X7R, 1210; Manufacturer: MuRata; TaMin_C: -55°C; Polarized: N; SizeAreaWB_mm2: 14.7; Value1: Unknown; U/M: EA; Value: 47uF; TaMax_C: 125°C; SizeZ_mm: 2.7; SizeX_mm: 3.2; SizeY_mm: 2.5; Cap_Case: 1210; SizeArea_mm2: 8; Cap_F: 47µF; AEC Category: Q200
C109-C111 C307-C309 = CMP-0007497-5: CAP, CERM, 10 uF, 10 V, +/- 20%, X7R, 0603; Manufacturer: MuRata; TaMin_C: -55°C; Polarized: N; SizeAreaWB_mm2: 4.68; Value1: Unknown; U/M: EA; Value: 10uF; TaMax_C: 125°C; SizeZ_mm: 1; SizeX_mm: 1.6; SizeY_mm: 0.8; SizeArea_mm2: 1.28; CompType: Capacitor; Cap_F: 10µF; AEC Category: Q200
C204 C207 C220 C359 C360 = CMP-0064970-1: CAP, CERM, 0.1 uF, 16 V,+/- 10%, X7R, 0201; Manufacturer: MuRata; TaMin_C: -55°C; Polarized: N; SizeAreaWB_mm2: 2.08; Value1: Unknown; U/M: EA; Value: 0.1uF; TaMax_C: 125°C; SizeZ_mm: 0.26; SizeX_mm: 0.6; SizeY_mm: 0.3; SizeArea_mm2: 0.18; Cap_F: 100nF; AEC Category: Q200
C205 C212-C214 = CMP-0007039-5: CAP, CERM, 0.1 uF, 25 V, +/- 10%, X7R, 0603; Manufacturer: TDK; TaMin_C: -55°C; Polarized: N; SizeAreaWB_mm2: 4.68; Value1: Unknown; U/M: EA; Value: 0.1uF; TaMax_C: 125°C; SizeZ_mm: 1; SizeX_mm: 1.6; SizeY_mm: 0.8; SizeArea_mm2: 1.28; Cap_F: 100nF; AEC Category: Q200
C206 = CMP-0007365-4: CAP, CERM, 1 uF, 10 V, +/- 10%, X7R, 0603; Manufacturer: MuRata; TaMin_C: -55°C; ESR_ohm: 0.011; Polarized: N; SizeAreaWB_mm2: 4.68; Value1: 0.011 ohm; U/M: EA; Value: 1uF; TaMax_C: 125°C; SizeZ_mm: 1; SizeX_mm: 1.6; SizeY_mm: 0.8; SizeArea_mm2: 1.28; Cap_F: 1µF; AEC Category: Q200
C208 = CMP-0007424-4: CAP, CERM, 0.47 uF, 25 V, +/- 10%, X7R, 0603; Manufacturer: MuRata; TaMin_C: -55°C; Polarized: N; SizeAreaWB_mm2: 4.68; Value1: Unknown; U/M: EA; Value: 0.47uF; TaMax_C: 125°C; SizeZ_mm: 1; SizeX_mm: 1.6; SizeY_mm: 0.8; SizeArea_mm2: 1.28; Cap_F: 470nF; AEC Category: Q200
C209-C211 = CMP-0008705-2: CAP, CERM, 10 uF, 35 V, +/- 10%, X7R, 1206; Manufacturer: TDK; TaMin_C: -55°C; ESR_ohm: 2.229m; Polarized: N; SizeAreaWB_mm2: 10.92; Value1: 0.002229 ohm; U/M: EA; Value: 10uF; TaMax_C: 125°C; SizeZ_mm: 1.8; SizeX_mm: 3.2; SizeY_mm: 1.6; SizeArea_mm2: 5.12; Cap_F: 10µF; IRMS_A: 4.85932A; AEC Category: Q200
C221 = CMP-0064936-4: CAP, CERM, 4.7 uF, 16 V,+/- 10%, X7R, 0603; Manufacturer: MuRata; TaMin_C: -55°C; Polarized: N; SizeAreaWB_mm2: 4.68; Value1: Unknown; U/M: EA; Value: 4.7uF; TaMax_C: 125°C; SizeZ_mm: 1; SizeX_mm: 1.6; SizeY_mm: 0.8; SizeArea_mm2: 1.28; Cap_F: 4.7µF; AEC Category: Q200
C222 = CMP-0009659-3: CAP, CERM, 22 pF, 25 V, +/- 5%, C0G/NP0, AEC-Q200 Grade 1, 0201; Manufacturer: MuRata; TaMin_C: -55°C; Polarized: N; SizeAreaWB_mm2: 2.08; Value1: Unknown; U/M: EA; Value: 22pF; TaMax_C: 125°C; SizeZ_mm: 0.33; SizeX_mm: 0.6; SizeY_mm: 0.3; Cap_Case: 0201; SizeArea_mm2: 0.18; AEC Qualified: Y; AEC Grade: 1; AEC Category: Q200
C223-C226 C229-C231 = CMP-0007497-5: CAP, CERM, 10 uF, 10 V, +/- 20%, X7R, 0603; Manufacturer: MuRata; TaMin_C: -55°C; Polarized: N; SizeAreaWB_mm2: 4.68; Value1: Unknown; U/M: EA; Value: 10uF; TaMax_C: 125°C; SizeZ_mm: 1; SizeX_mm: 1.6; SizeY_mm: 0.8; SizeArea_mm2: 1.28; Cap_F: 10µF; AEC Category: Q200
C227 C228 = CMP-0009732-1: CAP, CERM, 0.01 uF, 10 V, +/- 10%, X7R, 0201; Manufacturer: MuRata; TaMin_C: -55°C; Polarized: N; SizeAreaWB_mm2: 2.08; Value1: Unknown; U/M: EA; Value: 0.01uF; TaMax_C: 125°C; SizeZ_mm: 0.26; SizeX_mm: 0.6; SizeY_mm: 0.3; SizeArea_mm2: 0.18; Cap_F: 10nF; AEC Category: Q200
C235-C237 = CMP-0007730-2: CAP, CERM, 1 uF, 50 V, +/- 10%, X7R, 0805; Manufacturer: Kemet; TaMin_C: -55°C; Polarized: N; SizeAreaWB_mm2: 6.75; Value1: Unknown; U/M: EA; Value: 1uF; TaMax_C: 125°C; SizeZ_mm: 1.45; SizeX_mm: 2; SizeY_mm: 1.25; Cap_Case: 0805; SizeArea_mm2: 2.5; Cap_F: 1µF; AEC Category: Q200
C241 C242 = CMP-0009764-1: CAP, CERM, 1000 pF, 25 V, +/- 10%, X7R, 0201; Manufacturer: MuRata; TaMin_C: -55°C; Polarized: N; SizeAreaWB_mm2: 2.08; Value1: Unknown; U/M: EA; Value: 1000pF; TaMax_C: 125°C; SizeZ_mm: 0.33; SizeX_mm: 0.6; SizeY_mm: 0.3; Cap_Case: 0201; SizeArea_mm2: 0.18; Cap_F: 1nF; AEC Category: Q200
D6 = CMP-0028547-2: Diode, Schottky, 30 V, 1 A, SOD-123; Manufacturer: ON Semiconductor; Io_A: 1A; Green_Lifecycle: Active; SizeAreaWB_mm2: 13.095; Vr_V: 30V; Green_REACh: Passed; TJmax_C: 125°C; Value: 30V; SizeZ_mm: 1.35; SizeX_mm: 3.85; SizeY_mm: 1.7; Vf_V: 4.7dV; Value2: 0.47V; SizeArea_mm2: 6.545; AEC Category: Q101; RJC_CperW: 108
D7 = CMP-0006044-3: Diode, TVS, Bi, 15 V, 24.4 Vc, SMB; Manufacturer: Fairchild Semiconductor; Value1: 600W; Value: 15V; AEC Category: Q101; Ppk: 15kW
FB3 FB5-FB7 = CMP-0081829-1: 30 Ohms @ 100MHz 1 Power Line Ferrite Bead 0805 (2012 Metric) 8.5A 4mOhm; Manufacturer: Murata; SizeZ_mm: 1.05mm; Impedance At Frequency: 30Ω @ 100MHz; Symbol Name: SYM-BLM21SN300SN1D; AEC Qualified: No; DCR_ohm: 0.004Ω
J14 = CMP-0074940-1: Power Jack, mini, 2.1mm OD, R/A, TH; Manufacturer: Switchcraft; CNHeader: False; Green_Lifecycle: Not Set; Green_REACh: Incomplete
L17 = CMP-0061060-1: Inductor, Shielded, Composite, 10 uH, 8.7 A, 0.021 ohm, SMD; Manufacturer: Coilcraft; Isat: 11A @ 30% inductance drop; Irms: 8.7A @ 40C rise; Green_Lifecycle: Not Set; SizeAreaWB_mm2: 107.06; DCR_ohm: 0.021; Green_REACh: Incomplete; Value: 10uH; Imax_A: 8.7A; SizeZ_mm: 8; SizeX_mm: 8.1; SizeY_mm: 8.6; SizeArea_mm2: 69.66; Ind_H: 10µH; AEC Qualified: N; AEC Category: Q200
Q2 = CMP-0000207-1: MOSFET, N-CH, 20 V, 10 A, DQK0006C (WSON-6); Alternate Manufacturer: None; Manufacturer: Texas Instruments; SizeZ_mm: 0.8; ChType: N; Value2: 2.5 nC; Value1: 19; VdsMax_V: 20V; SizeX_mm: 2; Value: 20V; Rdson45_ohm: 19.2; SizeArea_mm2: 4; AEC Category: Q101; IdsMax_A: 10A; SizeAreaWB_mm2: 9; U/M: EA; QgTyp_nC: 2.5
R127-R129 R233 = CMP-0027615-1: RES, 33.0, 1%, 0.05 W, 0201; Manufacturer: Yageo America; Power_W: 50mW; TempCo: 200 ppm/C; Value_Code: 33R0; U/M: EA; Value: 33.0; Res_ohm: 33; SizeX_mm: 0.6; SizeY_mm: 0.3; SizeZ_mm: 0.26; Value2: 0.05W; SizeArea_mm2: 0.18; AEC Qualified: N; VDC_V: 25V; AEC Category: Q200
R130 R134 R136 R146 = CMP-0028107-1: RES, 4.99 k, 1%, 0.05 W, 0201; Manufacturer: Yageo America; Power_W: 50mW; TempCo: 200 ppm/C; Value_Code: 4k99; U/M: EA; Value: 4.99k; EIA_Code: E96; SizeX_mm: 0.6; SizeY_mm: 0.3; SizeZ_mm: 0.26; Value2: 0.05W; SizeArea_mm2: 0.18; AEC Qualified: N; VDC_V: 25V; AEC Category: Q200
R131 = CMP-0027685-1: RES, 3.00, 1%, 0.05 W, 0201; Manufacturer: Yageo America; Power_W: 50mW; TempCo: 350 ppm/C; Value_Code: 3R00; U/M: EA; Value: 3.00; Res_ohm: 3; SizeX_mm: 0.6; SizeY_mm: 0.3; SizeZ_mm: 0.26; Value2: 0.05W; SizeArea_mm2: 0.18; AEC Qualified: N; VDC_V: 25V; AEC Category: Q200
R132 = CMP-0028069-1: RES, 100 k, 1%, 0.05 W, 0201; Manufacturer: Yageo America; PartNumber: RC0201FS-7D100KL; Power_W: 50mW; TempCo: 200 ppm/C; U/M: EA; Value: 100k; EIA_Code: E96; SizeX_mm: 0.6; SizeY_mm: 0.3; SizeZ_mm: 0.26; Value2: 0.05W; SizeArea_mm2: 0.18; CompType: Resistor; AEC Qualified: N; VDC_V: 25V; AEC Category: Q200
R133 = CMP-0028027-1: RES, 49.9 k, 1%, 0.05 W, 0201; Manufacturer: Yageo America; Power_W: 50mW; TempCo: 200 ppm/C; Value_Code: 49k9; U/M: EA; Value: 49.9k; EIA_Code: E96; SizeX_mm: 0.6; SizeY_mm: 0.3; SizeZ_mm: 0.26; Value2: 0.05W; SizeArea_mm2: 0.18; AEC Qualified: N; VDC_V: 25V; AEC Category: Q200
R135 R137 R139-R143 = CMP-0027008-4: as R54 on sheet GPIO2_RevE2
R138 = CMP-0027418-1: RES, 19.1 k, 1%, 0.05 W, 0201; Manufacturer: Yageo America; Power_W: 50mW; TempCo: 200 ppm/C; Value_Code: 19k1; U/M: EA; Value: 19.1k; EIA_Code: E96; SizeX_mm: 0.6; SizeY_mm: 0.3; SizeZ_mm: 0.26; Value2: 0.05W; SizeArea_mm2: 0.18; AEC Qualified: N; VDC_V: 25V; AEC Category: Q200
R144 = CMP-0027974-1: RES, 1.00 M, 1%, 0.05 W, 0201; Manufacturer: Yageo America; Power_W: 50mW; TempCo: 200 ppm/C; Value_Code: 1M00; U/M: EA; Value: 1.00Meg; EIA_Code: E96; Res_ohm: 1M; SizeX_mm: 0.6; SizeY_mm: 0.3; SizeZ_mm: 0.26; Value2: 0.05W; SizeArea_mm2: 0.18; AEC Qualified: N; VDC_V: 25V; AEC Category: Q200
R145 = CMP-0028019-1: RES, 45.3 k, 1%, 0.05 W, 0201; Manufacturer: Yageo America; Power_W: 50mW; TempCo: 200 ppm/C; Value_Code: 45k3; U/M: EA; Value: 45.3k; EIA_Code: E96; SizeX_mm: 0.6; SizeY_mm: 0.3; SizeZ_mm: 0.26; Value2: 0.05W; SizeArea_mm2: 0.18; AEC Qualified: N; VDC_V: 25V; AEC Category: Q200
R175 R801 = CMP-0027945-1: as R75 on sheet GPIO2_RevE2
TP10 TP11 TP16 TP21 = CMP-0055137-1: Test Point, Miniature, Red, TH; Manufacturer: Keystone; CNHeader: FALSE; Green_Lifecycle: Active; Green_REACh: Passed; ContactFinish: Silver; CT: TRUE
U11 U57 = CMP-0051481-3: Single Positive-Edge-Triggered D-Type Flip-Flop With Clear and Preset, DQE0008A (X2SON-8); Manufacturer: Texas Instruments; Output Type: CMOS; Bits(#): 1; Input Type: CMOS/TTL; Technology Family: LVC; Schmitt Trigger: No; VCC(Max)(V): 5.5; Rating: Catalog; Output Drive (IOL/IOH)(Max)(mA): 32/-32; ICC @ Nom Voltage(Max)(mA): 0.01; VCC(Min)(V): 1.65; F @ Nom Voltage(Max)(Mhz): 150; Logic: True; Voltage(Nom)(V): 1.8,2.5,3.3,5; tpd @ Nom Voltage(Max)(ns): 13.4,7.1,5.9,4.1; AEC Category: Q200; CompType: IC
U12 = CMP-0035537-1: Single Output LDO, 150 mA, Fixed 3.3 V Output, 2.5 to 24 V Input, with Ultra-Low IQ, 5-pin SOT-23 (DBV), -40 to 85 degC, Green (RoHS & no Sb/Br); Manufacturer: Texas Instruments; Vout Adj(Max)(V): 3.3; Accuracy(%): 2; SubFamily: Single Channel LDO; Vin(Max)(V): 24; Iq(Typ)(mA): 0.032; Vin(Min)(V): 2.5; Iout(Max)(A): 0.15; Vdo(Typ)(mV): 400
U21 = CMP-0073871-3: High-Current (3 A), High-Accuracy (1%), Low-Noise (4.4 uVRMS), LDO Voltage Regulator, RGR0020A (VQFN-20); Alternate PartNumber: TPS7A8400RGRT; Alternate Manufacturer: Texas Instruments; Green_Lifecycle: Active; SizeAreaWB_mm2: 20.25; Green_REACh: Passed; SizeZ_mm: 1.0; SizeX_mm: 3.5; SizeArea_mm2: 12.25; CompType: IC; AEC Category: Q200; AEC Qualified: N
U22 = CMP-0074225-5: 12V, 5A, 30mΩ eFuse with Adjustable +/-15% Accurate Current Limit, DRC0010J (VSON-10); Alternate PartNumber: TPS259261DRCT; Alternate Manufacturer: Texas Instruments; Green_Lifecycle: Active; SizeAreaWB_mm2: 16; Green_REACh: Passed; SizeZ_mm: 1; SizeX_mm: 3; SizeArea_mm2: 9; CompType: IC; AEC Category: Q200; AEC Qualified: N; Rating: Catalog
U23 = CMP-0013906-5: 3.5A, 36V Synchronous, 400kHz, Step-Down Converter, RNL0022A (VQFN-HR-22); Manufacturer: Texas Instruments; Alternate PartNumber: LMS3635MQRNLTQ1; SizeX_mm: 4.0; SizeY_mm: 5.0; CompType: IC; SizeZ_mm: 0.9; SizeArea_mm2: 20.0; SizeAreaWB_mm2: 42.0; AEC Category: Q200; AEC Qualified: Y; Rating: Automotive
U58 = CMP-0051690-3: Single Inverter, DRL0005A, LARGE T&R; Manufacturer: Texas Instruments; Input Type: CMOS/TTL; 3-State Output: No; Voltage(Nom)(V): 1.8,2.5,3.3,5; Logic: Inverting; Technology Family: LVC; ICC @ Nom Voltage(Max)(mA): 0.01; Bits(#): 1; VCC(Max)(V): 5.5; Output Type: CMOS; Sub-Family: Inverting Buffer/Driver; tpd @ Nom Voltage(Max)(ns): 7.5,5.2,4.2,3.7; VCC(Min)(V): 1.65; Rating: Catalog; F @ Nom Voltage(Max)(Mhz): 150; Output Drive (IOL/IOH)(Max)(mA): 32/-32; AEC Category: Q200; AEC Qualified: N; CompType: IC; SizeX_mm: 1.6; SizeZ_mm: 0.6
Y3 = CMP-0006092-3: OSC, 1 MHz, 3.3V, SMD; Manufacturer: Fox Electronics; TaMin_C: -40°C; Frequency Stability: +/-25ppm; Frequency_Fixed: 1MHz; TaMax_C: 85°C; CompType: Oscillator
